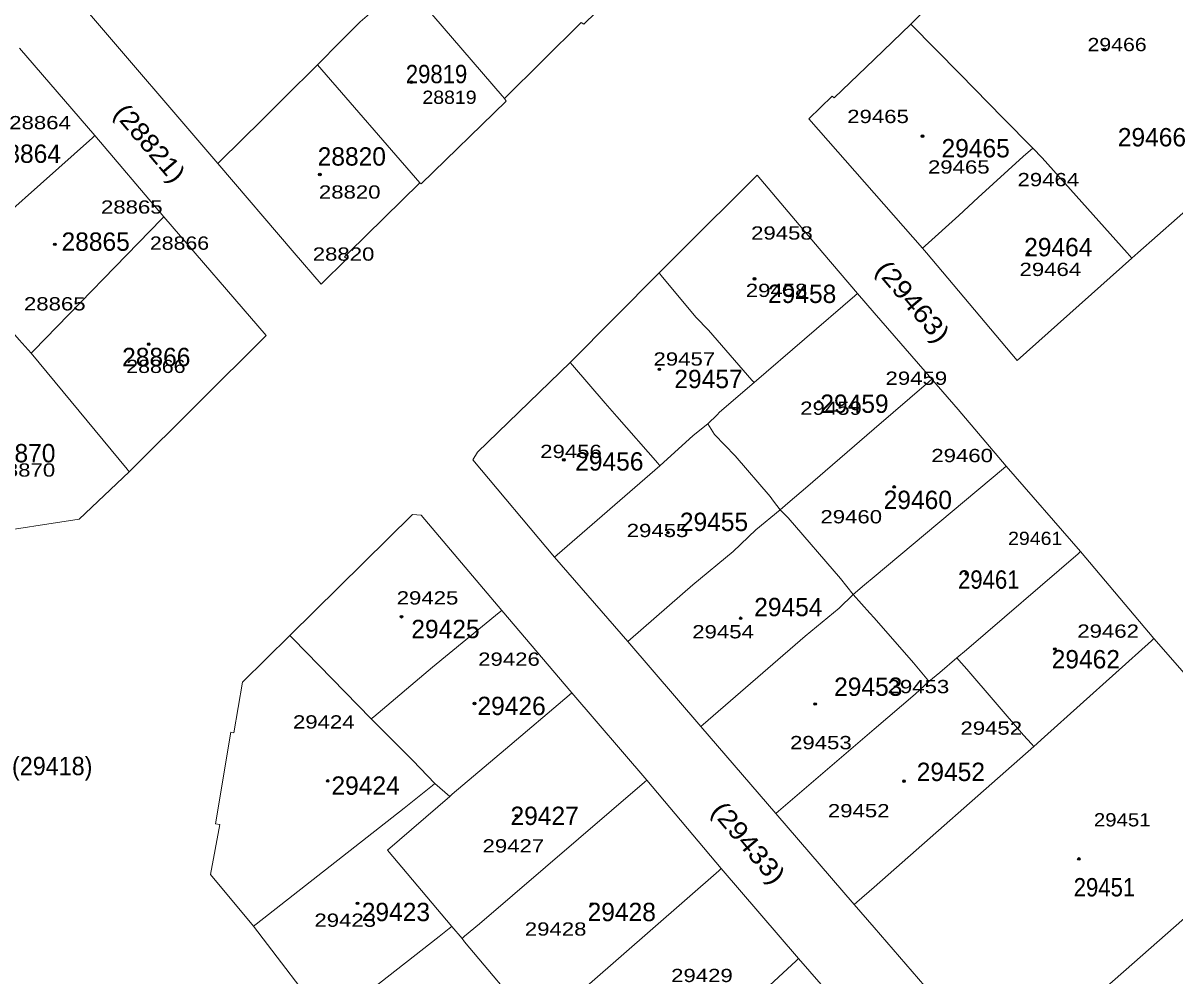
# Model space of a CAD drawing. Extents: x 650553 to 652508, y 239277 to 241647.
# Drawn here: x 651208.2 to 651434, y 240108.2 to 240295.1 of the extents above; entities that cross this region are included whole.
import ezdxf

# ---------------------------------------------------------------- set-up
doc = ezdxf.new("R2010")
doc.units = 0
doc.header["$PDMODE"] = 32
doc.header["$PDSIZE"] = 0.5
for name, color, linetype in [('19', 7, 'Continuous'), ('20', 7, 'Continuous'), ('6', 7, 'Continuous')]:
    doc.layers.add(name, color=color, linetype=linetype)
doc.layers.add('3', color=7, linetype='Continuous', lineweight=13)
doc.layers.add('5', color=7, linetype='Continuous', lineweight=13)

msp = doc.modelspace()

# ---------------------------------------------------------------- linework, layer by layer
at = {"layer": '3'}
for p, q in [((651382.18, 240294.85), (651375, 240287.91)), ((651375, 240261.73), (651384.51, 240250.92)), ((651375, 240238.21), (651386.291, 240225.211))]:
    msp.add_line(p, q, dxfattribs=at)
for points in [[(651426.69, 240250), (651461.4, 240280.6), (651417.67, 240330.87), (651412.21, 240325.69), (651412.52, 240325.19), (651382.18, 240294.85)], [(651302.06, 240323.02), (651322.74, 240299.4), (651318.09, 240294.84), (651317.54, 240295.2), (651302.54, 240280.28)], [(651285.91, 240263.75), (651271.96, 240250), (651271.2, 240249.25), (651271.62, 240248.84), (651266.6, 240243.84), (651261.32, 240250), (651246.32, 240267.52), (651220.02, 240298.27)], [(651255.84, 240233.78), (651235.77, 240257.09), (651222.25, 240273), (651207.46, 240290.15)], [(651375, 240287.91), (651367.2, 240280.38), (651366.79, 240280.75), (651362.23, 240276.26), (651375, 240261.73)], [(651302.54, 240280.28), (651302.84, 240279.76), (651286.22, 240263.52), (651285.91, 240263.75)], [(651364.98, 240250), (651352.08, 240265.26), (651336.8, 240250)], [(651384.51, 240250.92), (651385.28, 240250), (651403.03, 240228.87)], [(651336.8, 240250), (651332.85, 240246.06), (651315.44, 240228.49)], [(651375, 240238.21), (651371.72, 240242.03), (651364.98, 240250)], [(651403.03, 240228.87), (651425.53, 240248.98), (651426.69, 240250)], [(651172.78, 240201.91), (651181.85, 240192.05), (651219.16, 240197.79), (651228.97, 240207.08), (651255.84, 240233.78)], [(651315.44, 240228.49), (651297.22, 240210.92), (651296.35, 240209.4), (651312.35, 240190.34), (651326.71, 240173.81), (651341.01, 240157.09), (651355.74, 240140.05), (651371.11, 240122.2), (651375, 240117.7)], [(651386.291, 240225.211), (651391.457, 240219.264), (651400.87, 240208.15), (651415.49, 240191.42), (651429.87, 240174.36)], [(651302.02, 240179.87), (651286.18, 240198.53), (651284.49, 240198.66), (651260.454, 240174.948)], [(651375, 240094.57), (651373.49, 240096.32), (651360.19, 240111.6), (651345.04, 240129.24), (651330.47, 240146.6), (651315.74, 240163.7), (651302.02, 240179.87)], [(651260.454, 240174.948), (651251.16, 240165.78), (651249.5, 240155.87), (651248.88, 240155.98), (651245.9, 240138), (651246.7, 240137.86), (651244.93, 240128.08)], [(651429.87, 240174.36), (651455.086, 240145.538), (651455.493, 240146.045), (651459.75, 240140.58)], [(651459.75, 240140.58), (651399.97, 240087.93), (651395.8, 240092.84), (651396.15, 240093.24), (651375, 240117.7)], [(651244.93, 240128.08), (651253.33, 240117.93), (651267.91, 240098.88), (651285.64, 240076.82), (651301.47, 240056.95)]]:
    msp.add_lwpolyline(points, dxfattribs=at)
at = {"layer": '5'}
msp.add_line((651375, 240125.62), (651406.31, 240153.2), dxfattribs=at)
for points in [[(651265.85, 240286.89), (651270.4, 240291.47), (651274.26, 240295.31), (651275.6, 240296.49), (651282.58, 240303.46), (651287.57, 240308.19), (651293.09, 240314.01), (651302.06, 240323.02)], [(651282.58, 240303.46), (651302.109, 240280.78), (651302.54, 240280.28)], [(651382.18, 240294.85), (651391.86, 240285.06), (651400.23, 240276.51), (651406.12, 240270.52), (651407.94, 240268.62), (651424.62, 240250)], [(651285.91, 240263.75), (651265.85, 240286.89), (651259.39, 240280.49), (651255.09, 240276.17)], [(651255.09, 240276.17), (651246.82, 240268.013), (651246.32, 240267.52)], [(651222.25, 240273), (651221.75, 240272.555), (651194.72, 240248.495), (651194.22, 240248.05)], [(651406.12, 240270.52), (651404.25, 240268.93), (651395.43, 240260.84), (651391.61, 240257.35)], [(651209.75, 240230.35), (651210.237, 240230.85), (651235.283, 240256.59), (651235.77, 240257.09)], [(651391.61, 240257.35), (651385.01, 240251.373), (651384.51, 240250.92)], [(651190.76, 240251.59), (651194.22, 240248.05), (651207.38, 240232.92), (651209.75, 240230.35)], [(651425.53, 240248.98), (651425.084, 240249.48), (651424.62, 240250)], [(651332.85, 240246.06), (651333.266, 240245.56), (651340.03, 240237.42), (651342.56, 240234.85), (651351.028, 240225.06), (651351.46, 240224.56)], [(651371.72, 240242.03), (651371.22, 240241.599), (651351.46, 240224.56)], [(651209.75, 240230.35), (651228.557, 240207.58), (651228.97, 240207.08)], [(651315.44, 240228.49), (651315.868, 240227.99), (651322.27, 240220.52), (651324.53, 240217.88), (651332.569, 240208.76), (651333.01, 240208.26)], [(651351.46, 240224.56), (651344.68, 240218.77), (651344.22, 240218.26), (651342.41, 240216.48)], [(651375, 240215.46), (651385.72, 240224.718), (651386.291, 240225.211)], [(651342.41, 240216.48), (651339.5, 240214.16), (651333.01, 240208.26)], [(651342.41, 240216.48), (651342.725, 240215.98), (651343.74, 240214.37), (651347.76, 240210.18), (651354.59, 240202.19), (651355.28, 240201.3), (651356.61, 240199.6)], [(651375, 240215.46), (651361.55, 240203.85), (651358.53, 240201.33), (651356.61, 240199.6)], [(651333.01, 240208.26), (651312.85, 240190.774), (651312.35, 240190.34)], [(651375, 240186.45), (651400.37, 240207.731), (651400.87, 240208.15)], [(651356.61, 240199.6), (651351.83, 240195.67), (651347.37, 240191.41), (651339.46, 240184.92), (651327.21, 240174.246), (651326.71, 240173.81)], [(651356.61, 240199.6), (651358.15, 240198.03), (651368.44, 240186.12), (651370.91, 240182.99)], [(651391.2, 240170.6), (651393.12, 240172.17), (651414.99, 240190.99), (651415.49, 240191.42)], [(651375, 240186.45), (651373.13, 240184.88), (651370.91, 240182.99)], [(651370.91, 240182.99), (651368.16, 240180.35), (651361.51, 240174.83), (651341.51, 240157.523), (651341.01, 240157.09)], [(651370.91, 240182.99), (651374.18, 240179.37), (651375, 240178.44)], [(651276.43, 240158.61), (651276.93, 240159.032), (651288.44, 240168.74), (651301.52, 240179.46), (651302.02, 240179.87)], [(651375, 240178.44), (651382.75, 240169.62), (651385.322, 240166.47), (651385.73, 240165.97)], [(651260.454, 240174.948), (651261.029, 240174.36), (651276.43, 240158.61)], [(651406.31, 240153.2), (651408.41, 240155.06), (651429.37, 240173.91), (651429.87, 240174.36)], [(651385.73, 240165.97), (651387.86, 240167.73), (651391.2, 240170.6)], [(651391.2, 240170.6), (651391.635, 240170.1), (651393.15, 240168.36), (651404.3, 240155.44), (651405.861, 240153.7), (651406.31, 240153.2)], [(651375, 240156.58), (651383.03, 240163.48), (651385.73, 240165.97)], [(651291.79, 240143.39), (651292.29, 240143.814), (651302.75, 240152.69), (651315.24, 240163.276), (651315.74, 240163.7)], [(651276.43, 240158.61), (651284.57, 240150.45), (651288.91, 240145.96), (651291.79, 240143.39)], [(651375, 240156.58), (651356.24, 240140.479), (651355.74, 240140.05)], [(651288.91, 240145.96), (651288.41, 240145.558), (651282.89, 240141.12), (651253.83, 240118.322), (651253.33, 240117.93)], [(651294.23, 240115.55), (651294.73, 240115.968), (651297.66, 240118.42), (651329.97, 240146.171), (651330.47, 240146.6)], [(651291.79, 240143.39), (651279.63, 240132.86), (651292.21, 240117.87), (651294.23, 240115.55)], [(651345.04, 240129.24), (651344.54, 240128.803), (651312.49, 240100.79), (651310.68, 240098.95), (651309.28, 240098.02)], [(651375, 240125.62), (651371.61, 240122.64), (651371.11, 240122.2)], [(651292.21, 240117.87), (651291.71, 240117.48), (651289.7, 240115.91), (651268.41, 240099.271), (651267.91, 240098.88)], [(651294.23, 240115.55), (651294.68, 240114.85), (651307.73, 240099.48), (651309.28, 240098.02)], [(651336.33, 240089.52), (651359.69, 240111.137), (651360.19, 240111.6)]]:
    msp.add_lwpolyline(points, dxfattribs=at)
at = {"layer": '6'}
for p in [(651420.169, 240289.925), (651284.286, 240283.49), (651384.495, 240272.885), (651266.337, 240265.365), (651214.397, 240251.675), (651405.214, 240249.695), (651351.545, 240244.91), (651232.786, 240232.085), (651332.895, 240227.16), (651364.138, 240220.815), (651314.175, 240209.415), (651378.94, 240204.1), (651334.585, 240195.145), (651393.075, 240187.06), (651282.352, 240178.635), (651348.829, 240178.345), (651410.437, 240172.31), (651296.654, 240161.63), (651363.439, 240161.52), (651267.873, 240146.439), (651380.865, 240146.4), (651304.895, 240139.625), (651415.155, 240131.145), (651273.723, 240122.42), (651319.65, 240122.31)]:
    msp.add_point(p, dxfattribs=at)

# ---------------------------------------------------------------- texts
at = {"layer": '19'}
for s, width, p in [('29819', 0.9, (651283.193, 240283.277)), ('29461', 0.9, (651391.455, 240184.134)), ('(29418)', 0.95, (651205.987, 240147.56)), ('29451', 0.9, (651414.133, 240123.785))]:
    msp.add_text(s, height=3.6, dxfattribs=dict(at, width=width)).set_placement(p)
for s, rotation, width, p in [('(28821)', 310.357, 1.1, (651225.73, 240277.32)), ('(29463)', 310.22, 1.15, (651375.055, 240246.591)), ('(29433)', 310.006, 1.15, (651342.873, 240140.464))]:
    msp.add_text(s, height=3.6, rotation=rotation, dxfattribs=dict(at, width=width)).set_placement(p)
for s, p in [('29466', (651422.773, 240270.885)), ('28864', (651202.198, 240267.652)), ('29465', (651388.215, 240268.73)), ('28820', (651265.913, 240267.114)), ('28865', (651215.697, 240250.41)), ('29464', (651404.413, 240249.332)), ('29458', (651354.197, 240240.172)), ('28866', (651227.576, 240227.78)), ('29457', (651335.839, 240223.468)), ('29459', (651364.457, 240218.619)), ('28870', (651201.118, 240208.921)), ('29456', (651316.4, 240207.303)), ('29460', (651376.875, 240199.76)), ('29455', (651336.918, 240195.449)), ('29454', (651351.496, 240178.745)), ('29425', (651284.273, 240174.435)), ('29462', (651409.814, 240168.508)), ('29453', (651367.156, 240163.119)), ('29426', (651297.233, 240159.348)), ('29452', (651383.355, 240146.416)), ('29424', (651268.613, 240143.722)), ('29427', (651303.713, 240137.795)), ('29423', (651274.553, 240118.936)), ('29428', (651318.831, 240118.936))]:
    msp.add_text(s, height=3.6, dxfattribs=at).set_placement(p)
at = {"layer": '20'}
for s, width, p in [('29466', 1.2, (651416.832, 240289.559)), ('28819', 1.1, (651286.439, 240279.219)), ('29465', 1.25, (651369.727, 240275.458)), ('28864', 1.25, (651205.438, 240274.246)), ('29465', 1.25, (651385.556, 240265.55)), ('29464', 1.25, (651403.113, 240263.077)), ('28820', 1.25, (651266.152, 240260.642)), ('28865', 1.25, (651223.428, 240257.699)), ('28866', 1.2, (651233.024, 240250.616)), ('29458', 1.25, (651350.883, 240252.601)), ('28820', 1.25, (651264.944, 240248.472)), ('29464', 1.25, (651403.505, 240245.463)), ('29458', 1.25, (651349.84, 240241.349)), ('28865', 1.25, (651208.33, 240238.713)), ('28866', 1.2, (651228.401, 240226.444)), ('29457', 1.25, (651331.75, 240227.894)), ('29459', 1.25, (651377.24, 240224.121)), ('29459', 1.25, (651360.512, 240218.242)), ('29456', 1.25, (651309.535, 240209.764)), ('29460', 1.25, (651386.214, 240208.957)), ('28870', 1.25, (651202.366, 240206.116)), ('29460', 1.25, (651364.471, 240196.951)), ('29455', 1.25, (651326.5, 240194.257)), ('29461', 1.1, (651401.263, 240192.711)), ('29425', 1.25, (651281.404, 240181.04)), ('29454', 1.25, (651339.346, 240174.39)), ('29462', 1.25, (651414.832, 240174.524)), ('29426', 1.25, (651297.38, 240169.022)), ('29453', 1.25, (651377.648, 240163.646)), ('29424', 1.25, (651261.067, 240156.711)), ('29452', 1.25, (651391.923, 240155.495)), ('29453', 1.25, (651358.522, 240152.66)), ('29452', 1.25, (651365.938, 240139.301)), ('29451', 1.15, (651418.083, 240137.514)), ('29427', 1.25, (651298.235, 240132.401)), ('29423', 1.25, (651265.269, 240117.826)), ('29428', 1.25, (651306.525, 240116.093)), ('29429', 1.25, (651335.203, 240106.985))]:
    msp.add_text(s, height=2.6, dxfattribs=dict(at, width=width)).set_placement(p)

doc.saveas('drawing.dxf')
